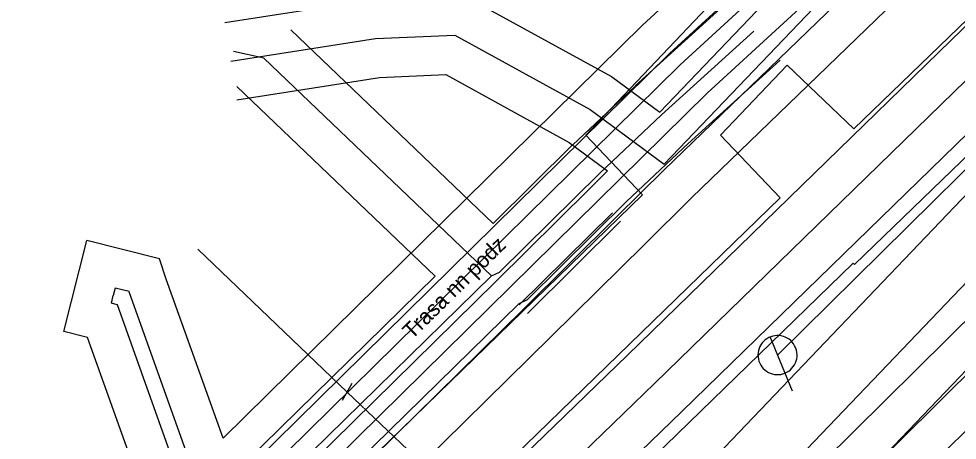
# Model space of a CAD drawing. Extents: x -762993 to -761845, y -975230 to -974501.
# Drawn here: x -762256.7 to -762232.71, y -974968.01 to -974957.23 of the extents above; entities that cross this region are included whole.
import ezdxf

# ---------------------------------------------------------------- set-up
doc = ezdxf.new("R2010")
doc.units = 0
for name, color, linetype in [('IS_CETIN_chranicka', 7, 'Continuous'), ('IS_CETIN_OP', 7, 'Continuous'), ('IS_CETIN_podzem metalika zam', 7, 'Continuous'), ('IS_CETIN_podzem optika zam', 7, 'Continuous'), ('IS_CEZ-D_anotace', 7, 'Continuous'), ('IS_CEZ-D_el vedeni NN podzem', 7, 'Continuous'), ('IS_CEZ-D_OP', 7, 'Continuous'), ('IS_CEZ-T_parovod', 7, 'Continuous'), ('IS_CEZ-T_parovod OP', 7, 'Continuous'), ('IS_DPmUL_OP', 7, 'Continuous'), ('IS_DPmUL_VO vedeni podzem', 7, 'Continuous'), ('IS_GASNET_plyn NTL rad', 7, 'Continuous'), ('IS_GASNET_plyn OP', 7, 'Continuous'), ('IS_SCVK_kanalizace jednotna', 7, 'Continuous'), ('IS_SCVK_kanalizace znaky', 7, 'Continuous'), ('IS_SCVK_vodovod OP', 7, 'Continuous'), ('IS_SCVK_vodovod pripojky', 7, 'Continuous'), ('IS_SCVK_vodovod privadec', 7, 'Continuous'), ('IS_SCVK_vodovod znaky', 7, 'Continuous'), ('IS_T-Mobile_OP', 7, 'Continuous'), ('IS_T-Mobile_podzem optika', 7, 'Continuous')]:
    doc.layers.add(name, color=color, linetype=linetype)

msp = doc.modelspace()

# ---------------------------------------------------------------- linework, layer by layer
at = {"layer": 'IS_CETIN_chranicka'}
for points in [[(-762243.906, -974964.553), (-762241.526, -974962.193)], [(-762243.694, -974964.767), (-762241.314, -974962.407)]]:
    msp.add_lwpolyline(points, dxfattribs=at)
at = {"layer": 'IS_CETIN_OP'}
for points in [[(-762240.314, -974959.621), (-762235.368, -974954.443), (-762229.198, -974948.525), (-762226.125, -974945.639), (-762225.209, -974944.624), (-762223.108, -974942.602)], [(-762224.35, -974947.167), (-762239.502, -974961.816), (-762240.717, -974963.012), (-762243.097, -974965.371), (-762252.983, -974975.106)], [(-762251.435, -974957.332), (-762247.68, -974956.743), (-762245.314, -974956.639), (-762241.549, -974958.706), (-762240.314, -974959.621)], [(-762251.125, -974959.308), (-762247.48, -974958.737), (-762245.786, -974958.661), (-762242.631, -974960.394), (-762241.648, -974961.122)], [(-762241.648, -974961.122), (-762242.123, -974961.588), (-762244.503, -974963.949), (-762254.387, -974973.68)]]:
    msp.add_lwpolyline(points, dxfattribs=at)
at = {"layer": 'IS_CETIN_podzem metalika zam'}
for points in [[(-762225.045, -974946.448), (-762240.2, -974961.1), (-762241.42, -974962.3), (-762243.8, -974964.66), (-762253.685, -974974.393)], [(-762251.28, -974958.32), (-762247.58, -974957.74), (-762245.55, -974957.65), (-762242.09, -974959.55), (-762240.2, -974960.95)]]:
    msp.add_lwpolyline(points, dxfattribs=at)
at = {"layer": 'IS_CETIN_podzem optika zam'}
msp.add_lwpolyline([(-762240.2, -974960.95), (-762234.66, -974955.15), (-762228.51, -974949.25), (-762225.41, -974946.34), (-762224.49, -974945.32), (-762221.81, -974942.74)], dxfattribs=at)
at = {"layer": 'IS_CEZ-D_el vedeni NN podzem'}
for points in [[(-762247.847, -974984.536), (-762246.114, -974982.893), (-762246.05, -974980.697), (-762253.7, -974972.107), (-762252.057, -974970.493), (-762250.973, -974969.428), (-762239.791, -974958.41), (-762235.916, -974954.845), (-762234.541, -974953.31), (-762221.186, -974940.477), (-762220.991, -974940.306), (-762216.22, -974936.128), (-762203.456, -974923.483), (-762203.186, -974923.213), (-762202.673, -974922.708), (-762197.126, -974917.211), (-762182.367, -974902.622)], [(-762234.834, -974953.037), (-762236.201, -974954.564), (-762240.067, -974958.12), (-762251.254, -974969.143), (-762251.891, -974969.769), (-762252.332, -974968.535), (-762253.876, -974964.216), (-762253.878, -974964.21), (-762254.236, -974964.12), (-762254.284, -974964.314)], [(-762244.131, -974983.395), (-762243.698, -974982.98), (-762244.256, -974982.397), (-762245.738, -974980.442), (-762253.68, -974971.528), (-762252.205, -974970.078), (-762252.708, -974968.669), (-762254.179, -974964.552), (-762254.181, -974964.546), (-762254.333, -974964.508), (-762254.284, -974964.314)]]:
    msp.add_lwpolyline(points, dxfattribs=at)
at = {"layer": 'IS_CEZ-D_OP'}
for points in [[(-762252.034, -974971.872), (-762251.356, -974971.206), (-762250.272, -974970.141), (-762239.101, -974959.134), (-762235.203, -974955.548), (-762233.821, -974954.005), (-762220.51, -974941.214), (-762220.332, -974941.058), (-762215.538, -974936.86), (-762202.751, -974924.192), (-762202.482, -974923.923), (-762201.97, -974923.419), (-762196.423, -974917.922), (-762181.665, -974903.334)], [(-762235.579, -974952.37), (-762236.914, -974953.861), (-762240.757, -974957.396), (-762251.476, -974967.958), (-762252.931, -974963.89), (-762253.103, -974963.374), (-762254.96, -974962.907)], [(-762254.633, -974971.962), (-762255.06, -974971.482), (-762253.362, -974969.813), (-762253.65, -974969.005), (-762254.943, -974965.386), (-762255.548, -974965.235), (-762254.96, -974962.907)]]:
    msp.add_lwpolyline(points, dxfattribs=at)
at = {"layer": 'IS_CEZ-T_parovod'}
msp.add_lwpolyline([(-762252.5, -975008.59), (-762252.58, -975007.19), (-762253.19, -974987.18), (-762253.2, -974985.67), (-762257.54, -974981.54), (-762246.7, -974971.01), (-762237.24, -974961.81), (-762238.76, -974960.21), (-762237.06, -974958.42), (-762235.35, -974960.05), (-762220.52, -974945.72), (-762219.73, -974944.77), (-762200.92, -974926.55), (-762198.18, -974929.41), (-762193.38, -974924.68)], dxfattribs=at)
at = {"layer": 'IS_CEZ-T_parovod OP'}
for points in [[(-762254.996, -975008.733), (-762255.078, -975007.299), (-762255.69, -974987.226), (-762255.693, -974986.749), (-762261.147, -974981.559), (-762248.442, -974969.217), (-762240.754, -974961.74), (-762242.208, -974960.21), (-762237.148, -974954.882), (-762235.362, -974956.585), (-762222.355, -974944.017), (-762221.566, -974943.068), (-762200.854, -974923.005), (-762198.129, -974925.85), (-762195.116, -974922.881)], [(-762250.004, -975008.447), (-762250.082, -975007.081), (-762250.69, -974987.134), (-762250.707, -974984.591), (-762253.933, -974981.521), (-762244.958, -974972.803), (-762235.373, -974963.482), (-762235.338, -974963.515), (-762218.685, -974947.423), (-762217.894, -974946.472), (-762200.986, -974930.095), (-762198.231, -974932.97), (-762193.371, -974928.181)]]:
    msp.add_lwpolyline(points, dxfattribs=at)
at = {"layer": 'IS_DPmUL_OP'}
for p, q in [((-762244.874, -974977.229), (-762228.861, -974961.348)), ((-762243.466, -974978.649), (-762227.465, -974962.78))]:
    msp.add_line(p, q, dxfattribs=at)
at = {"layer": 'IS_DPmUL_VO vedeni podzem'}
msp.add_lwpolyline([(-762244.17, -974977.939), (-762228.163, -974962.064)], dxfattribs=at)
at = {"layer": 'IS_GASNET_plyn NTL rad'}
msp.add_lwpolyline([(-762254.38, -974980.34), (-762254.3, -974980.18), (-762254.49, -974979.97), (-762249.33, -974975.11), (-762246.79, -974972.7), (-762240.45, -974966.56), (-762232.17, -974958.5), (-762223.94, -974950.53), (-762218.08, -974944.94), (-762212.07, -974939.13), (-762200.83, -974928.57), (-762199.24, -974927.03), (-762198.4, -974925.79), (-762191.542, -974918.748)], dxfattribs=at)
at = {"layer": 'IS_GASNET_plyn OP'}
msp.add_lwpolyline([(-762231.473, -974959.217), (-762239.753, -974967.277), (-762246.098, -974973.422), (-762248.643, -974975.837), (-762253.287, -974980.211), (-762253.268, -974980.351), (-762253.406, -974980.627), (-762253.486, -974980.787), (-762253.671, -974981.158), (-762254.457, -974981.42), (-762254.827, -974981.234), (-762255.198, -974981.049), (-762255.394, -974980.462), (-762255.506, -974980.338), (-762255.473, -974979.522), (-762255.176, -974979.242), (-762250.017, -974974.383), (-762247.482, -974971.978), (-762241.147, -974965.843), (-762232.867, -974957.783), (-762224.633, -974949.809)], dxfattribs=at)
at = {"layer": 'IS_SCVK_kanalizace jednotna'}
msp.add_lwpolyline([(-762237.305, -974965.834), (-762203.442, -974932.379)], dxfattribs=at)
at = {"layer": 'IS_SCVK_kanalizace znaky'}
for points in [[(-762236.843, -974965.643), (-762236.866, -974965.594), (-762236.895, -974965.548), (-762236.929, -974965.504), (-762236.967, -974965.465), (-762237.01, -974965.43), (-762237.056, -974965.4), (-762237.105, -974965.376), (-762237.155, -974965.357), (-762237.209, -974965.343), (-762237.263, -974965.336), (-762237.318, -974965.334), (-762237.373, -974965.339), (-762237.426, -974965.349), (-762237.479, -974965.366), (-762237.529, -974965.387), (-762237.576, -974965.415), (-762237.621, -974965.447), (-762237.661, -974965.483), (-762237.697, -974965.525), (-762237.729, -974965.569), (-762237.755, -974965.617), (-762237.776, -974965.668), (-762237.792, -974965.721), (-762237.801, -974965.774), (-762237.805, -974965.829), (-762237.802, -974965.883), (-762237.794, -974965.938), (-762237.78, -974965.99), (-762237.76, -974966.042), (-762237.734, -974966.09), (-762237.704, -974966.136), (-762237.668, -974966.177), (-762237.629, -974966.215), (-762237.586, -974966.248), (-762237.538, -974966.276), (-762237.489, -974966.299), (-762237.437, -974966.317), (-762237.383, -974966.328), (-762237.329, -974966.334), (-762237.274, -974966.333), (-762237.22, -974966.327), (-762237.166, -974966.315), (-762237.114, -974966.297), (-762237.065, -974966.273), (-762237.019, -974966.244), (-762236.976, -974966.211), (-762236.936, -974966.172), (-762236.902, -974966.13), (-762236.872, -974966.084), (-762236.846, -974966.035), (-762236.828, -974965.984), (-762236.814, -974965.931), (-762236.806, -974965.877), (-762236.805, -974965.822), (-762236.809, -974965.767), (-762236.819, -974965.713), (-762236.836, -974965.66), (-762236.843, -974965.643)], [(-762236.922, -974966.758), (-762237.496, -974965.372)]]:
    msp.add_lwpolyline(points, dxfattribs=at)
at = {"layer": 'IS_SCVK_vodovod OP'}
for points in [[(-762217.473, -974947.113), (-762218.81, -974948.43), (-762220.343, -974950.02), (-762232.223, -974961.467), (-762242.519, -974972.237), (-762258.353, -974987.594)], [(-762215.297, -974949.321), (-762216.606, -974950.61), (-762218.151, -974952.212), (-762230.027, -974963.655), (-762240.319, -974974.421), (-762256.335, -974989.956)]]:
    msp.add_lwpolyline(points, dxfattribs=at)
at = {"layer": 'IS_SCVK_vodovod pripojky'}
for points in [[(-762248.308, -974966.779), (-762252.125, -974963.122)], [(-762241.419, -974973.329), (-762248.308, -974966.779)]]:
    msp.add_lwpolyline(points, dxfattribs=at)
at = {"layer": 'IS_SCVK_vodovod privadec'}
msp.add_lwpolyline([(-762216.385, -974948.217), (-762217.708, -974949.52), (-762219.247, -974951.116), (-762231.125, -974962.561), (-762241.419, -974973.329), (-762257.344, -974988.775)], dxfattribs=at)
at = {"layer": 'IS_SCVK_vodovod znaky'}
msp.add_lwpolyline([(-762248.183, -974966.562), (-762248.433, -974966.995)], dxfattribs=at)
at = {"layer": 'IS_T-Mobile_OP'}
for p, q in [((-762244.576, -974962.468), (-762249.748, -974957.518)), ((-762246.058, -974963.818), (-762251.13, -974958.962)), ((-762244.576, -974962.468), (-762242.553, -974960.469)), ((-762259.72, -974977.2), (-762246.058, -974963.818)), ((-762243.707, -974964.421), (-762243.92, -974964.524)), ((-762258.76, -974979.06), (-762243.92, -974964.524))]:
    msp.add_line(p, q, dxfattribs=at)
for points in [[(-762240.942, -974958.948), (-762238.584, -974956.809)], [(-762239.598, -974960.43), (-762237.24, -974958.291)], [(-762242.536, -974960.453), (-762240.956, -974958.962)], [(-762241.164, -974961.907), (-762239.584, -974960.416)], [(-762243.707, -974964.421), (-762241.147, -974961.891)]]:
    msp.add_lwpolyline(points, dxfattribs=at)
at = {"layer": 'IS_T-Mobile_podzem optika'}
for points in [[(-762240.27, -974959.689), (-762237.912, -974957.55)], [(-762240.27, -974959.689), (-762237.912, -974957.55)], [(-762250.439, -974958.24), (-762251.21, -974958.069)], [(-762250.439, -974958.24), (-762251.21, -974958.069)], [(-762244.62, -974963.81), (-762250.439, -974958.24)], [(-762244.62, -974963.81), (-762250.439, -974958.24)], [(-762241.85, -974961.18), (-762240.27, -974959.689)], [(-762241.85, -974961.18), (-762240.27, -974959.689)], [(-762244.41, -974963.71), (-762241.85, -974961.18)], [(-762244.41, -974963.71), (-762241.85, -974961.18)], [(-762244.62, -974963.81), (-762244.41, -974963.71)], [(-762244.62, -974963.81), (-762244.41, -974963.71)], [(-762259.24, -974978.13), (-762244.62, -974963.81)], [(-762259.24, -974978.13), (-762244.62, -974963.81)]]:
    msp.add_lwpolyline(points, dxfattribs=at)

# ---------------------------------------------------------------- texts
at = {"layer": 'IS_CEZ-D_anotace'}
msp.add_text('Trasa nn podz', height=0.4, rotation=44.5769, dxfattribs=at).set_placement((-762246.65, -974965.449))

doc.saveas('drawing.dxf')
